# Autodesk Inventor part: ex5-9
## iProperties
Created: 2007-01
Part Number: ex5-9
Document SubType Name: Modeling
Designer: E. MOSS ext 5-2222
Manufacturer: Standard
Standards Organization: Custom
Density: 1 g/cm^3
Mass: 1519.63 g
Surface Area: 1009.43 cm^2
Volume: 1519.63 cm^3
Author: E. MOSS ext 5-2222
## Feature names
1. Extrusion1
2. base round [Revolution]
3. Split3
4. Hole11
5. Mirror17
6. monitor support slot [Extrusion]
7. Fillet23
8. arm recess [Extrusion]
9. arm-mounts [Hole]
10. arm mounting pattern holes [Rectangular Pattern]
11. Extrusion38
12. Fillet24
13. Hole13
14. Hole14
15. Extrusion40
16. Hole15
17. Hole16
18. front panel recess [Extrusion]
19. Hole17
20. rear panel recess [Extrusion]
21. Hole18
